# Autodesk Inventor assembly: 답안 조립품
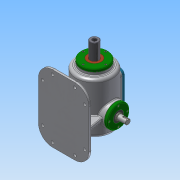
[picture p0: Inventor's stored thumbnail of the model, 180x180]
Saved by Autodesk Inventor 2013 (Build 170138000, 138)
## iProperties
Created: 2019-10
Part Number: 답안 조립품
Document SubType Name: Assembly
Designer: Administrator
Mass: 7821.81 g
Surface Area: 4928.07 cm^2
Volume: 2176.15 cm^3
Density: 3.59434 g/cm^3
Author: Administrator
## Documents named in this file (17)
- C:\Users\Administrator\Desktop\새 폴더\답안 조립품.iam
- C:\Users\Administrator\Desktop\새 폴더\본체.ipt
- C:\Users\Administrator\Desktop\새 폴더\개스킷 A.ipt
- C:\Users\Administrator\Desktop\새 폴더\개스킷 B.ipt
- C:\Users\Administrator\Desktop\새 폴더\고정플레이트.ipt
- C:\Users\Administrator\Desktop\새 폴더\베어링 6205.ipt
- 베어링 6205.ipt
- C:\Users\Administrator\Desktop\새 폴더\볼트 M4x0.7.ipt
- C:\Users\Administrator\Desktop\새 폴더\부시.ipt
- C:\Users\Administrator\Desktop\새 폴더\상부커버.ipt
- C:\Users\Administrator\Desktop\새 폴더\슬라이드 커버.ipt
- C:\Users\Administrator\Desktop\새 폴더\슬라이드.ipt
- C:\Users\Administrator\Desktop\새 폴더\오일 실 25 38 8.ipt
- C:\Users\Administrator\Desktop\새 폴더\육각머리볼트 M4.ipt
- C:\Users\Administrator\Desktop\새 폴더\축 커버.ipt
- C:\Users\Administrator\Desktop\새 폴더\편심축.ipt
- C:\Users\Administrator\Desktop\새 폴더\가변 스프링.ipt
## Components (17 placed, 5 different names)
1. 개스킷 A:1
2. 개스킷 B:1
3. 고정플레이트:1 — 각도:2, 플러쉬:1
4. 개스킷 B:2
5. M4x0.7:5
6. M4x0.7:6
7. M4x0.7:7
8. M4x0.7:8
9. 가변 스프링:1
10. M4x0.7:1
11. M4x0.7:2
12. M4x0.7:3
13. M4x0.7:4
14. M4x0.7:9
15. M4x0.7:10
16. M4x0.7:11
17. M4x0.7:12
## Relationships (2: Angle 1, Flush 1)
- 각도:2 [Angle]: 고정플레이트:1
- 플러쉬:1 [Flush]: 고정플레이트:1
